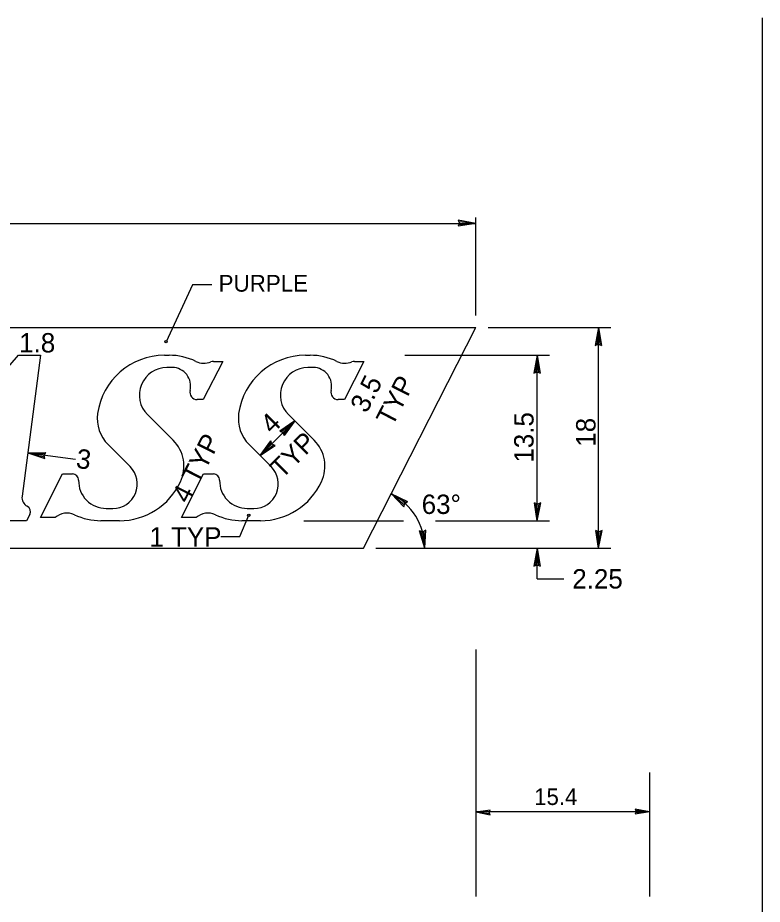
# Model space of a CAD drawing. Extents: x 10268197 to 10268739, y 2141503 to 2142677.
# Drawn here: x 10268632.91 to 10268664.32, y 2142394.16 to 2142431.59 of the extents above; entities that cross this region are included whole.
import ezdxf

# ---------------------------------------------------------------- set-up
doc = ezdxf.new("R2010")
doc.units = 0
for name, color, linetype in [('1', 7, 'Continuous'), ('21', 7, 'Continuous'), ('Default', 7, 'Continuous'), ('NonPlottingEle_dp', 7, 'Continuous')]:
    doc.layers.add(name, color=color, linetype=linetype)

msp = doc.modelspace()

# ---------------------------------------------------------------- linework, layer by layer
at = {"layer": '1'}
for p, q in [((10268652.242, 2142419.022), (10268652.242, 2142423.161)), ((10268629.787, 2142422.903), (10268652.242, 2142422.903)), ((10268640.279, 2142420.318), (10268639.164, 2142417.911)), ((10268641.101, 2142420.318), (10268640.279, 2142420.318)), ((10268652.759, 2142418.504), (10268657.934, 2142418.504)), ((10268657.416, 2142409.19), (10268657.416, 2142418.504)), ((10268649.24, 2142417.34), (10268655.346, 2142417.34)), ((10268654.829, 2142410.354), (10268654.829, 2142417.34)), ((10268643.134, 2142413.104), (10268644.598, 2142414.567)), ((10268633.327, 2142413.217), (10268635.344, 2142412.954)), ((10268642.275, 2142409.694), (10268642.655, 2142410.582)), ((10268644.984, 2142410.354), (10268649.178, 2142410.354)), ((10268650.531, 2142410.354), (10268655.346, 2142410.354)), ((10268641.471, 2142409.694), (10268642.275, 2142409.694)), ((10268648.013, 2142409.19), (10268657.934, 2142409.19)), ((10268654.829, 2142407.897), (10268654.829, 2142409.19)), ((10268654.829, 2142407.897), (10268655.954, 2142407.897)), ((10268652.242, 2142404.921), (10268652.242, 2142394.488)), ((10268659.562, 2142399.73), (10268659.562, 2142394.488)), ((10268659.004, 2142398.068), (10268658.956, 2142397.962)), ((10268659.562, 2142398.058), (10268658.956, 2142397.962)), ((10268659.562, 2142398.058), (10268658.96, 2142398.175)), ((10268658.96, 2142398.175), (10268659.004, 2142398.068)), ((10268659.562, 2142398.058), (10268658.982, 2142398.018)), ((10268659.562, 2142398.058), (10268658.983, 2142398.119))]:
    msp.add_line(p, q, dxfattribs=at)
for centre in [(10268639.164, 2142417.91), (10268642.655, 2142410.581)]:
    msp.add_circle(centre, 0.0517, dxfattribs=at)
msp.add_arc((10268647.496, 2142409.19), 2.587, 0, 63.0012, dxfattribs=at)
at = {"layer": '21'}
for p, q in [((10268652.242, 2142398.058), (10268652.847, 2142398.154)), ((10268652.242, 2142398.058), (10268652.822, 2142398.099)), ((10268652.242, 2142398.058), (10268652.844, 2142397.942)), ((10268652.242, 2142398.058), (10268652.82, 2142397.998)), ((10268652.799, 2142398.049), (10268652.847, 2142398.154)), ((10268652.844, 2142397.942), (10268652.799, 2142398.049))]:
    msp.add_line(p, q, dxfattribs=at)
at = {"layer": 'Default'}
for p, q in [((10268651.545, 2142422.914), (10268651.485, 2142422.782)), ((10268652.242, 2142422.903), (10268651.49, 2142423.048)), ((10268651.49, 2142423.048), (10268651.545, 2142422.914)), ((10268652.242, 2142422.903), (10268651.519, 2142422.978)), ((10268652.242, 2142422.903), (10268651.485, 2142422.782)), ((10268652.242, 2142422.903), (10268651.517, 2142422.852)), ((10268622.725, 2142418.504), (10268652.242, 2142418.504)), ((10268647.496, 2142409.19), (10268652.242, 2142418.504)), ((10268657.416, 2142418.504), (10268657.27, 2142417.752)), ((10268657.416, 2142418.504), (10268657.341, 2142417.782)), ((10268657.416, 2142418.504), (10268657.536, 2142417.748)), ((10268657.416, 2142418.504), (10268657.467, 2142417.78)), ((10268657.27, 2142417.752), (10268657.404, 2142417.808)), ((10268657.404, 2142417.808), (10268657.536, 2142417.748)), ((10268627.648, 2142411.263), (10268632.932, 2142417.34)), ((10268632.932, 2142417.34), (10268633.864, 2142417.34)), ((10268633.864, 2142417.34), (10268633.089, 2142411.385)), ((10268639.097, 2142417.34), (10268639.293, 2142417.34)), ((10268645.048, 2142417.34), (10268645.244, 2142417.34)), ((10268654.829, 2142417.34), (10268654.683, 2142416.588)), ((10268654.829, 2142417.34), (10268654.753, 2142416.617)), ((10268654.829, 2142417.34), (10268654.949, 2142416.583)), ((10268654.829, 2142417.34), (10268654.88, 2142416.615)), ((10268641.559, 2142417.081), (10268640.736, 2142415.467)), ((10268641.171, 2142417.081), (10268641.559, 2142417.081)), ((10268647.509, 2142417.081), (10268646.687, 2142415.467)), ((10268647.121, 2142417.081), (10268647.509, 2142417.081)), ((10268639.425, 2142416.822), (10268639.203, 2142416.822)), ((10268645.375, 2142416.822), (10268645.153, 2142416.822)), ((10268654.683, 2142416.588), (10268654.817, 2142416.644)), ((10268654.817, 2142416.644), (10268654.949, 2142416.583)), ((10268640.736, 2142415.467), (10268640.478, 2142415.467)), ((10268646.687, 2142415.467), (10268646.428, 2142415.467)), ((10268638.38, 2142414.835), (10268639.464, 2142413.75)), ((10268644.33, 2142414.835), (10268645.415, 2142413.75)), ((10268644.598, 2142414.567), (10268643.963, 2142414.139)), ((10268644.598, 2142414.567), (10268644.033, 2142414.11)), ((10268644.598, 2142414.567), (10268644.121, 2142414.019)), ((10268644.598, 2142414.567), (10268644.148, 2142413.948)), ((10268643.963, 2142414.139), (10268644.097, 2142414.083)), ((10268644.097, 2142414.083), (10268644.148, 2142413.948)), ((10268637.649, 2142412.639), (10268636.718, 2142413.569)), ((10268643.599, 2142412.639), (10268642.669, 2142413.569)), ((10268643.134, 2142413.104), (10268643.584, 2142413.724)), ((10268643.134, 2142413.104), (10268643.611, 2142413.652)), ((10268643.134, 2142413.104), (10268643.699, 2142413.562)), ((10268643.634, 2142413.588), (10268643.584, 2142413.724)), ((10268643.769, 2142413.532), (10268643.634, 2142413.588)), ((10268633.327, 2142413.217), (10268634.092, 2142413.238)), ((10268633.327, 2142413.217), (10268634.053, 2142412.975)), ((10268633.327, 2142413.217), (10268634.034, 2142413.048)), ((10268633.327, 2142413.217), (10268634.052, 2142413.174)), ((10268634.016, 2142413.115), (10268634.092, 2142413.238)), ((10268643.134, 2142413.104), (10268643.769, 2142413.532)), ((10268634.053, 2142412.975), (10268634.016, 2142413.115)), ((10268633.86, 2142410.484), (10268634.799, 2142412.328)), ((10268634.799, 2142412.328), (10268635.215, 2142412.328)), ((10268639.81, 2142410.484), (10268640.75, 2142412.328)), ((10268640.75, 2142412.328), (10268641.166, 2142412.328)), ((10268648.671, 2142411.495), (10268649.359, 2142411.16)), ((10268648.671, 2142411.495), (10268649.203, 2142410.944)), ((10268648.671, 2142411.495), (10268649.22, 2142411.019)), ((10268648.671, 2142411.495), (10268649.293, 2142411.121)), ((10268649.203, 2142410.944), (10268649.234, 2142411.087)), ((10268649.234, 2142411.087), (10268649.359, 2142411.16)), ((10268654.829, 2142410.354), (10268654.709, 2142411.111)), ((10268654.841, 2142411.051), (10268654.709, 2142411.111)), ((10268654.829, 2142410.354), (10268654.778, 2142411.079)), ((10268654.829, 2142410.354), (10268654.975, 2142411.106)), ((10268654.829, 2142410.354), (10268654.904, 2142411.078)), ((10268654.975, 2142411.106), (10268654.841, 2142411.051)), ((10268633.413, 2142410.621), (10268633.277, 2142410.354)), ((10268636.637, 2142410.872), (10268636.917, 2142410.872)), ((10268642.588, 2142410.872), (10268642.867, 2142410.872)), ((10268633.277, 2142410.354), (10268630.69, 2142410.354)), ((10268634.489, 2142410.484), (10268633.86, 2142410.484)), ((10268637.195, 2142410.354), (10268636.417, 2142410.354)), ((10268640.439, 2142410.484), (10268639.81, 2142410.484)), ((10268643.145, 2142410.354), (10268642.367, 2142410.354)), ((10268650.083, 2142409.19), (10268649.859, 2142409.923)), ((10268649.998, 2142409.882), (10268649.859, 2142409.923)), ((10268650.083, 2142409.19), (10268649.933, 2142409.901)), ((10268650.123, 2142409.955), (10268649.998, 2142409.882)), ((10268650.083, 2142409.19), (10268650.058, 2142409.917)), ((10268650.083, 2142409.19), (10268650.123, 2142409.955)), ((10268657.416, 2142409.19), (10268657.296, 2142409.947)), ((10268657.428, 2142409.887), (10268657.296, 2142409.947)), ((10268657.416, 2142409.19), (10268657.365, 2142409.915)), ((10268657.416, 2142409.19), (10268657.562, 2142409.942)), ((10268657.416, 2142409.19), (10268657.491, 2142409.913)), ((10268657.562, 2142409.942), (10268657.428, 2142409.887)), ((10268622.038, 2142409.19), (10268647.496, 2142409.19)), ((10268654.829, 2142409.19), (10268654.683, 2142408.439)), ((10268654.829, 2142409.19), (10268654.753, 2142408.468)), ((10268654.829, 2142409.19), (10268654.949, 2142408.434)), ((10268654.829, 2142409.19), (10268654.88, 2142408.466)), ((10268654.683, 2142408.439), (10268654.817, 2142408.494)), ((10268654.817, 2142408.494), (10268654.949, 2142408.434)), ((10268659.562, 2142398.058), (10268652.242, 2142398.058))]:
    msp.add_line(p, q, dxfattribs=at)
for centre, radius, start, end in [((10268639.097, 2142414.493), 2.846, 90, 172.3089), ((10268639.293, 2142414.752), 2.587, 64.0896, 90), ((10268645.048, 2142414.493), 2.846, 90, 172.3089), ((10268645.244, 2142414.752), 2.587, 64.0896, 90), ((10268640.763, 2142417.777), 0.776, 244.0896, 292.0347), ((10268641.171, 2142416.77), 0.31, 90, 112.0347), ((10268646.713, 2142417.777), 0.776, 244.0896, 292.0347), ((10268647.121, 2142416.77), 0.31, 90, 112.0347), ((10268639.203, 2142415.657), 1.164, 90, 225), ((10268639.425, 2142416.046), 0.776, 345.6915, 90), ((10268645.153, 2142415.657), 1.164, 90, 225), ((10268645.375, 2142416.046), 0.776, 345.6915, 90), ((10268640.478, 2142415.777), 0.31, 165.6915, 270), ((10268646.428, 2142415.777), 0.31, 165.6915, 270), ((10268637.815, 2142414.666), 1.552, 172.3089, 225), ((10268643.766, 2142414.666), 1.552, 172.3089, 225), ((10268638.367, 2142412.652), 1.552, 334.95, 45), ((10268644.317, 2142412.652), 1.552, 334.95, 45), ((10268636.917, 2142411.906), 1.035, 270, 45), ((10268642.867, 2142411.906), 1.035, 270, 45), ((10268635.215, 2142412.069), 0.259, 358.6664, 90), ((10268636.638, 2142412.035), 1.164, 178.6665, 270), ((10268641.166, 2142412.069), 0.259, 358.6664, 90), ((10268642.588, 2142412.035), 1.164, 178.6665, 270), ((10268637.195, 2142413.2), 2.846, 270, 334.95), ((10268643.145, 2142413.2), 2.846, 270, 334.95), ((10268633.499, 2142411.331), 0.414, 172.5884, 241.8673), ((10268633.182, 2142410.738), 0.259, 332.9784, 61.8673), ((10268634.984, 2142409.955), 0.724, 64.3795, 133.1892), ((10268636.416, 2142412.941), 2.587, 244.3795, 270), ((10268640.935, 2142409.955), 0.724, 64.3795, 133.1892), ((10268642.367, 2142412.941), 2.587, 244.3795, 270)]:
    msp.add_arc(centre, radius, start, end, dxfattribs=at)
at = {"layer": 'NonPlottingEle_dp'}
msp.add_line((10268664.322, 2142431.588), (10268664.322, 2142335.588), dxfattribs=at)

# ---------------------------------------------------------------- texts
at = {"layer": '1'}
for s, height, p in [('PURPLE', 0.706, (10268641.381, 2142420.024)), ('1.8', 0.8187, (10268632.966, 2142417.456)), ('63°', 0.8187, (10268649.951, 2142410.639)), ('1 TYP', 0.8187, (10268638.46, 2142409.261)), ('2.25', 0.8187, (10268656.306, 2142407.491)), ('15.4', 0.7, (10268654.697, 2142398.353))]:
    msp.add_text(s, height=height, dxfattribs=at).set_placement(p)
for s, height, rotation, p in [('3.5', 0.8187, 63, (10268647.626, 2142414.857)), ('TYP', 0.8187, 63, (10268648.721, 2142414.299)), ('4', 0.819, 45, (10268643.643, 2142413.975)), ('13.5', 0.8187, 90, (10268654.673, 2142412.806)), ('18', 0.8187, 90, (10268657.286, 2142413.479)), ('4 TYP', 0.8187, 62.9993, (10268640.105, 2142411.036)), ('TYP', 0.8187, 45, (10268644.051, 2142412.09)), ('3', 0.819, 352.5994, (10268635.336, 2142412.588))]:
    msp.add_text(s, height=height, rotation=rotation, dxfattribs=at).set_placement(p)

doc.saveas('drawing.dxf')
